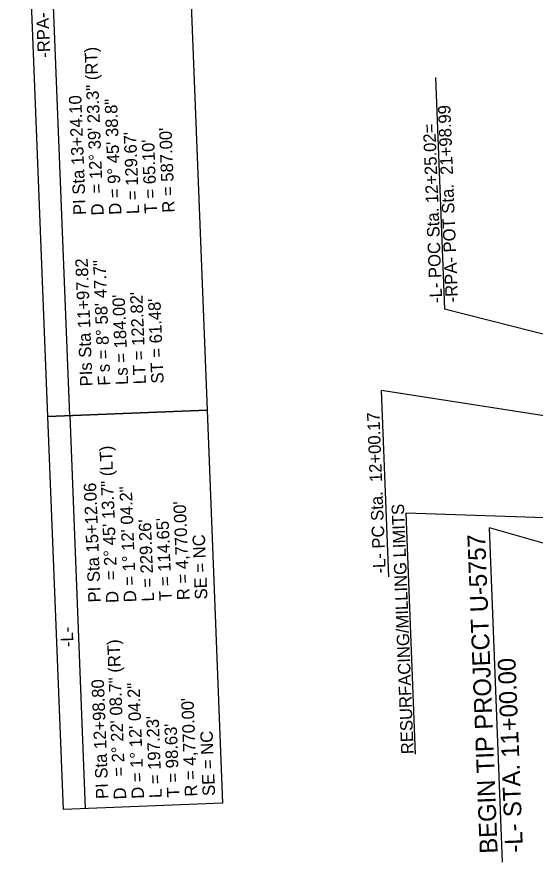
# Model space of a CAD drawing. Extents: x 1627861 to 1629601, y 761281 to 766239.
# Drawn here: x 1627982.2 to 1628273.7, y 761457.9 to 761933.4 of the extents above; entities that cross this region are included whole.
import ezdxf

# ---------------------------------------------------------------- set-up
doc = ezdxf.new("R2010")
doc.units = 0
for name, color, linetype in [('Exist Other Culture Sign Leader', 7, 'Continuous'), ('Exist Right of Way Line Leader', 7, 'Continuous'), ('Exist Utilities Gas UG Line Text', 7, 'Continuous'), ('Exist Utilities Power UG Cable SUE LOS B Cogo Point CELL', 7, 'Continuous'), ('Scratch_Level_0', 7, 'Continuous')]:
    doc.layers.add(name, color=color, linetype=linetype)

msp = doc.modelspace()

# ---------------------------------------------------------------- linework, layer by layer
at = {"layer": 'Exist Right of Way Line Leader'}
for p, q in [((1628217.57, 761899.23), (1628222.71, 761768.94)), ((1628489.94, 761700.98), (1628222.71, 761768.94)), ((1628490.64, 761675.93), (1628187.22, 761723.24)), ((1628191.35, 761618.32), (1628187.22, 761723.24))]:
    msp.add_line(p, q, dxfattribs=at)
at = {"layer": 'Exist Utilities Gas UG Line Text'}
for q in [(1627994.5, 762151.23), (1628020.66, 761488.01)]:
    msp.add_line((1628011.94, 761709.08), q, dxfattribs=at)
for points in [[(1627999.6, 761708.6), (1627982.17, 762150.75), (1628071.71, 762154.28), (1628089.14, 761712.13)], [(1628008.32, 761487.52), (1627999.6, 761708.6), (1628089.14, 761712.13), (1628097.86, 761491.05)]]:
    msp.add_lwpolyline(points, close=True, dxfattribs=at)
at = {"layer": 'Scratch_Level_0'}
for p, q in [((1628200.87, 761654.13), (1628206.22, 761518.52)), ((1628438.54, 761646.09), (1628200.87, 761654.13)), ((1628255.36, 761457.87), (1628247.94, 761645.94)), ((1628495.4, 761575.57), (1628247.94, 761645.94))]:
    msp.add_line(p, q, dxfattribs=at)

# ---------------------------------------------------------------- texts
at = {"layer": 'Exist Other Culture Sign Leader'}
for s, p in [('BEGIN TIP PROJECT U-5757', (1628252.63, 761462.81)), ('-L- STA. 11+00.00', (1628266.89, 761463.37))]:
    msp.add_text(s, height=10, rotation=92.2582, dxfattribs=at).set_placement(p)
at = {"layer": 'Exist Right of Way Line Leader'}
for s, p in [('-RPA- POT Sta.  21+98.99', (1628230.35, 761772.92)), ('-L- POC Sta. 12+25.02= ', (1628221.48, 761772.57)), ('-L- PC Sta.  12+00.17', (1628189.66, 761620.34))]:
    msp.add_text(s, height=7, rotation=92.2582, dxfattribs=at).set_placement(p)
at = {"layer": 'Exist Utilities Gas UG Line Text'}
for s, rotation, p in [('-RPA-', 92.2582, (1628000.95, 761910.56)), ('= 12%%d 39\' 23.3" (RT)', 92.2582, (1628030.43, 761834.19)), ('PI Sta 13+24.10', 92.2582, (1628021.02, 761822.08)), ('D = 9%%d 45\' 38.8"', 92.2582, (1628041.03, 761822.19)), ("R = 587.00'", 92.2582, (1628071.01, 761823.37)), ("L = 129.67'", 92.2582, (1628051.02, 761822.59)), ("T = 65.10'", 92.2582, (1628061.01, 761822.98)), ('D', 92.2582, (1628031.04, 761821.8)), ('PIs Sta 11+97.82', 92.2582, (1628024.8, 761725.66)), ('s = 8%%d 58\' 47.7"', 92.2582, (1628034.5, 761733.57)), ("Ls = 184.00'", 92.2582, (1628044.79, 761726.45)), ("LT = 122.82'", 92.2582, (1628054.78, 761726.84)), ("ST = 61.48'", 92.2582, (1628064.77, 761727.24)), ('F', 92.2582, (1628034.8, 761726.06)), ('= 2%%d 45\' 13.7" (LT)', 92.2582, (1628038.57, 761616.61)), ('PI Sta 15+12.06', 92.2582, (1628029.36, 761604.07)), ('D = 1%%d 12\' 04.2"', 92.2582, (1628049.37, 761604.18)), ("R = 4,770.00'", 92.2582, (1628079.34, 761605.36)), ("T = 114.65'", 92.2582, (1628069.35, 761604.97)), ("L = 229.26'", 92.2582, (1628059.36, 761604.57)), ('SE = NC', 92.2589, (1628089.34, 761605.76)), ('D', 92.2582, (1628039.37, 761603.79)), ('-L-', 92.2582, (1628014.03, 761578.95)), ('= 2%%d 22\' 08.7" (RT)', 92.2589, (1628042.93, 761506.08)), ('PI Sta 12+98.80', 92.2589, (1628033.71, 761493.53)), ('D = 1%%d 12\' 04.2"', 92.2589, (1628053.73, 761493.64)), ("R = 4,770.00'", 92.2589, (1628083.7, 761494.83)), ("L = 197.23'", 92.2589, (1628063.72, 761494.04)), ("T = 98.63'", 92.2589, (1628073.71, 761494.43)), ('SE = NC', 92.2589, (1628093.69, 761495.22)), ('D', 92.2589, (1628043.73, 761493.25))]:
    msp.add_text(s, height=7, rotation=rotation, dxfattribs=at).set_placement(p)
at = {"layer": 'Exist Utilities Power UG Cable SUE LOS B Cogo Point CELL'}
msp.add_text('RESURFACING/MILLING LIMITS', height=7, rotation=92.2582, dxfattribs=at).set_placement((1628205.41, 761518.72))

doc.saveas('drawing.dxf')
